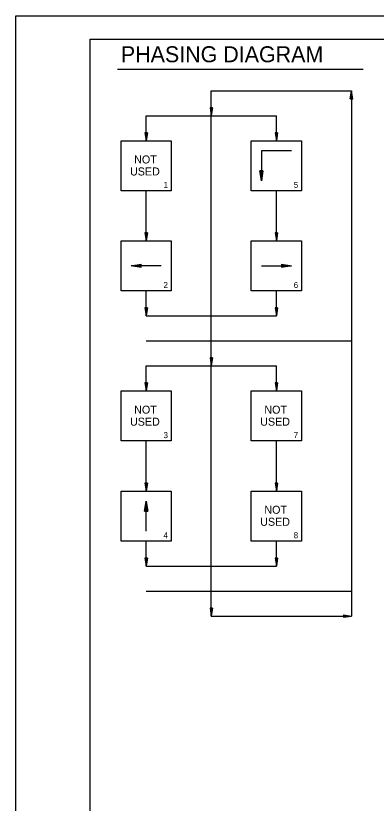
# Model space of a CAD drawing. Extents: x 1736833 to 1738623, y 544707 to 545544.
# Drawn here: x 1737623.4 to 1737803.3, y 544953.4 to 545346.8 of the extents above; entities that cross this region are included whole.
import ezdxf

# ---------------------------------------------------------------- set-up
doc = ezdxf.new("R2010")
doc.units = 0
for name, color, linetype in [('R_Border', 7, 'Continuous'), ('R_Draft', 7, 'Continuous'), ('R_No Plot', 7, 'Continuous'), ('T_Drafting', 7, 'Continuous'), ('T_Notes', 7, 'Continuous')]:
    doc.layers.add(name, color=color, linetype=linetype)

msp = doc.modelspace()

# ---------------------------------------------------------------- linework, layer by layer
at = {"layer": 'R_Border'}
for p, q in [((1737660.6, 545335.14), (1738609.14, 545335.14)), ((1737660.6, 544718.76), (1737660.6, 545335.14))]:
    msp.add_line(p, q, dxfattribs=at)
at = {"layer": 'R_Draft'}
msp.add_lwpolyline([(1737660.6, 545335.14), (1738362.36, 545335.14), (1738362.36, 545305.5), (1738475, 545295.74), (1738536.2, 545296.37), (1738536.2, 545224.37), (1738536.2, 545185.59), (1738536.2, 545175.9), (1738608.92, 545175.9), (1738609.14, 544767.79), (1738408.07, 544767.79), (1738257.64, 544767.79), (1738257.64, 544719.22), (1737660.6, 544718.76)], close=True, dxfattribs=at)
at = {"layer": 'R_No Plot'}
msp.add_line((1737623.4, 545346.82), (1738623.4, 545346.82), dxfattribs=at)
msp.add_lwpolyline([(1737623.38, 545346.82), (1738623.4, 545346.82), (1738623.4, 544706.81), (1737623.38, 544706.81)], close=True, dxfattribs=at)
at = {"layer": 'T_Drafting'}
for p, q in [((1737720.98, 545046.89), (1737720.98, 545309.39)), ((1737720.98, 545309.39), (1737790.98, 545309.39)), ((1737790.38, 545305.39), (1737790.98, 545309.39)), ((1737790.48, 545305.39), (1737790.98, 545308.73)), ((1737790.58, 545305.39), (1737790.98, 545308.04)), ((1737790.68, 545305.39), (1737790.98, 545307.37)), ((1737790.78, 545305.39), (1737790.98, 545306.69)), ((1737790.88, 545305.39), (1737790.98, 545306.03)), ((1737790.98, 545309.39), (1737790.98, 545046.89)), ((1737791.58, 545305.39), (1737790.98, 545309.39)), ((1737791.48, 545305.39), (1737790.98, 545308.73)), ((1737791.37, 545305.39), (1737790.98, 545308.04)), ((1737791.27, 545305.39), (1737790.98, 545307.37)), ((1737791.17, 545305.39), (1737790.98, 545306.69)), ((1737791.07, 545305.39), (1737790.98, 545306.03)), ((1737790.38, 545305.39), (1737791.58, 545305.39)), ((1737720.38, 545300.89), (1737720.98, 545296.89)), ((1737721.58, 545300.89), (1737720.38, 545300.89)), ((1737720.48, 545300.89), (1737720.98, 545297.56)), ((1737720.58, 545300.89), (1737720.98, 545298.25)), ((1737720.68, 545300.89), (1737720.98, 545298.92)), ((1737720.78, 545300.89), (1737720.98, 545299.59)), ((1737720.88, 545300.89), (1737720.98, 545300.26)), ((1737721.58, 545300.89), (1737720.98, 545296.89)), ((1737721.17, 545300.89), (1737720.98, 545299.59)), ((1737721.37, 545300.89), (1737720.98, 545298.25)), ((1737721.48, 545300.89), (1737720.98, 545297.56)), ((1737721.27, 545300.89), (1737720.98, 545298.92)), ((1737721.07, 545300.89), (1737720.98, 545300.26)), ((1737688.48, 545284.39), (1737688.48, 545296.89)), ((1737688.48, 545296.89), (1737753.48, 545296.89)), ((1737753.48, 545284.39), (1737753.48, 545296.89)), ((1737687.88, 545288.39), (1737688.48, 545284.39)), ((1737689.08, 545288.39), (1737687.88, 545288.39)), ((1737687.98, 545288.39), (1737688.48, 545285.06)), ((1737688.08, 545288.39), (1737688.48, 545285.75)), ((1737688.18, 545288.39), (1737688.48, 545286.42)), ((1737688.28, 545288.39), (1737688.48, 545287.09)), ((1737688.38, 545288.39), (1737688.48, 545287.76)), ((1737689.08, 545288.39), (1737688.48, 545284.39)), ((1737688.67, 545288.39), (1737688.48, 545287.09)), ((1737688.87, 545288.39), (1737688.48, 545285.75)), ((1737688.98, 545288.39), (1737688.48, 545285.06)), ((1737688.77, 545288.39), (1737688.48, 545286.42)), ((1737688.57, 545288.39), (1737688.48, 545287.76)), ((1737752.88, 545288.39), (1737753.48, 545284.39)), ((1737754.08, 545288.39), (1737752.88, 545288.39)), ((1737752.98, 545288.39), (1737753.48, 545285.06)), ((1737753.08, 545288.39), (1737753.48, 545285.75)), ((1737753.18, 545288.39), (1737753.48, 545286.42)), ((1737753.28, 545288.39), (1737753.48, 545287.09)), ((1737753.38, 545288.39), (1737753.48, 545287.76)), ((1737754.08, 545288.39), (1737753.48, 545284.39)), ((1737753.67, 545288.39), (1737753.48, 545287.09)), ((1737753.87, 545288.39), (1737753.48, 545285.75)), ((1737753.98, 545288.39), (1737753.48, 545285.06)), ((1737753.77, 545288.39), (1737753.48, 545286.42)), ((1737753.57, 545288.39), (1737753.48, 545287.76)), ((1737760.98, 545279.39), (1737745.98, 545279.39)), ((1737745.98, 545279.39), (1737745.98, 545264.39)), ((1737745.98, 545264.39), (1737745.23, 545269.39)), ((1737746.73, 545269.39), (1737745.23, 545269.39)), ((1737745.35, 545269.39), (1737745.98, 545265.23)), ((1737745.98, 545266.09), (1737745.48, 545269.39)), ((1737745.6, 545269.39), (1737745.98, 545266.92)), ((1737745.98, 545267.77), (1737745.73, 545269.39)), ((1737745.86, 545269.39), (1737745.98, 545268.6)), ((1737745.98, 545268.6), (1737746.09, 545269.39)), ((1737746.22, 545269.39), (1737745.98, 545267.77)), ((1737745.98, 545266.92), (1737746.35, 545269.39)), ((1737746.47, 545269.39), (1737745.98, 545266.09)), ((1737745.98, 545265.23), (1737746.6, 545269.39)), ((1737746.73, 545269.39), (1737745.98, 545264.39)), ((1737688.48, 545234.39), (1737688.48, 545259.39)), ((1737753.48, 545234.39), (1737753.48, 545259.39)), ((1737687.88, 545238.39), (1737688.48, 545234.39)), ((1737689.08, 545238.39), (1737687.88, 545238.39)), ((1737687.98, 545238.39), (1737688.48, 545235.06)), ((1737688.08, 545238.39), (1737688.48, 545235.75)), ((1737688.18, 545238.39), (1737688.48, 545236.42)), ((1737688.28, 545238.39), (1737688.48, 545237.09)), ((1737688.38, 545238.39), (1737688.48, 545237.76)), ((1737689.08, 545238.39), (1737688.48, 545234.39)), ((1737688.67, 545238.39), (1737688.48, 545237.09)), ((1737688.87, 545238.39), (1737688.48, 545235.75)), ((1737688.98, 545238.39), (1737688.48, 545235.06)), ((1737688.77, 545238.39), (1737688.48, 545236.42)), ((1737688.57, 545238.39), (1737688.48, 545237.76)), ((1737752.88, 545238.39), (1737753.48, 545234.39)), ((1737754.08, 545238.39), (1737752.88, 545238.39)), ((1737752.98, 545238.39), (1737753.48, 545235.06)), ((1737753.08, 545238.39), (1737753.48, 545235.75)), ((1737753.18, 545238.39), (1737753.48, 545236.42)), ((1737753.28, 545238.39), (1737753.48, 545237.09)), ((1737753.38, 545238.39), (1737753.48, 545237.76)), ((1737754.08, 545238.39), (1737753.48, 545234.39)), ((1737753.67, 545238.39), (1737753.48, 545237.09)), ((1737753.87, 545238.39), (1737753.48, 545235.75)), ((1737753.98, 545238.39), (1737753.48, 545235.06)), ((1737753.77, 545238.39), (1737753.48, 545236.42)), ((1737753.57, 545238.39), (1737753.48, 545237.76)), ((1737680.98, 545221.89), (1737685.98, 545222.64)), ((1737695.98, 545221.89), (1737680.98, 545221.89)), ((1737685.98, 545221.14), (1737680.98, 545221.89)), ((1737685.98, 545222.52), (1737681.81, 545221.89)), ((1737681.81, 545221.89), (1737685.98, 545221.27)), ((1737682.67, 545221.89), (1737685.98, 545222.39)), ((1737685.98, 545221.4), (1737682.67, 545221.89)), ((1737685.98, 545222.27), (1737683.5, 545221.89)), ((1737683.5, 545221.89), (1737685.98, 545221.52)), ((1737684.35, 545221.89), (1737685.98, 545222.14)), ((1737685.98, 545221.65), (1737684.35, 545221.89)), ((1737685.98, 545222.01), (1737685.19, 545221.89)), ((1737685.19, 545221.89), (1737685.98, 545221.78)), ((1737685.98, 545221.14), (1737685.98, 545222.64)), ((1737745.98, 545221.89), (1737760.98, 545221.89)), ((1737755.98, 545222.64), (1737760.98, 545221.89)), ((1737755.98, 545222.64), (1737755.98, 545221.14)), ((1737760.14, 545221.89), (1737755.98, 545222.52)), ((1737755.98, 545222.39), (1737759.28, 545221.89)), ((1737758.45, 545221.89), (1737755.98, 545222.27)), ((1737755.98, 545222.14), (1737757.6, 545221.89)), ((1737756.77, 545221.89), (1737755.98, 545222.01)), ((1737760.98, 545221.89), (1737755.98, 545221.14)), ((1737755.98, 545221.27), (1737760.14, 545221.89)), ((1737759.28, 545221.89), (1737755.98, 545221.4)), ((1737755.98, 545221.52), (1737758.45, 545221.89)), ((1737757.6, 545221.89), (1737755.98, 545221.65)), ((1737755.98, 545221.78), (1737756.77, 545221.89)), ((1737688.48, 545196.89), (1737688.48, 545209.39)), ((1737753.48, 545196.89), (1737753.48, 545209.39)), ((1737687.88, 545200.89), (1737688.48, 545196.89)), ((1737689.08, 545200.89), (1737687.88, 545200.89)), ((1737687.98, 545200.89), (1737688.48, 545197.56)), ((1737688.08, 545200.89), (1737688.48, 545198.25)), ((1737688.18, 545200.89), (1737688.48, 545198.92)), ((1737688.28, 545200.89), (1737688.48, 545199.59)), ((1737688.38, 545200.89), (1737688.48, 545200.26)), ((1737689.08, 545200.89), (1737688.48, 545196.89)), ((1737688.67, 545200.89), (1737688.48, 545199.59)), ((1737688.87, 545200.89), (1737688.48, 545198.25)), ((1737688.98, 545200.89), (1737688.48, 545197.56)), ((1737688.77, 545200.89), (1737688.48, 545198.92)), ((1737688.57, 545200.89), (1737688.48, 545200.26)), ((1737752.88, 545200.89), (1737753.48, 545196.89)), ((1737754.08, 545200.89), (1737752.88, 545200.89)), ((1737752.98, 545200.89), (1737753.48, 545197.56)), ((1737753.08, 545200.89), (1737753.48, 545198.25)), ((1737753.18, 545200.89), (1737753.48, 545198.92)), ((1737753.28, 545200.89), (1737753.48, 545199.59)), ((1737753.38, 545200.89), (1737753.48, 545200.26)), ((1737754.08, 545200.89), (1737753.48, 545196.89)), ((1737753.67, 545200.89), (1737753.48, 545199.59)), ((1737753.87, 545200.89), (1737753.48, 545198.25)), ((1737753.98, 545200.89), (1737753.48, 545197.56)), ((1737753.77, 545200.89), (1737753.48, 545198.92)), ((1737753.57, 545200.89), (1737753.48, 545200.26)), ((1737688.48, 545196.89), (1737753.48, 545196.89)), ((1737688.48, 545184.39), (1737790.98, 545184.39)), ((1737720.38, 545175.89), (1737720.98, 545171.89)), ((1737721.58, 545175.89), (1737720.38, 545175.89)), ((1737720.48, 545175.89), (1737720.98, 545172.56)), ((1737720.58, 545175.89), (1737720.98, 545173.25)), ((1737720.68, 545175.89), (1737720.98, 545173.92)), ((1737720.78, 545175.89), (1737720.98, 545174.59)), ((1737720.88, 545175.89), (1737720.98, 545175.26)), ((1737721.58, 545175.89), (1737720.98, 545171.89)), ((1737721.17, 545175.89), (1737720.98, 545174.59)), ((1737721.37, 545175.89), (1737720.98, 545173.25)), ((1737721.48, 545175.89), (1737720.98, 545172.56)), ((1737721.27, 545175.89), (1737720.98, 545173.92)), ((1737721.07, 545175.89), (1737720.98, 545175.26)), ((1737688.48, 545171.89), (1737753.48, 545171.89)), ((1737688.48, 545159.39), (1737688.48, 545171.89)), ((1737753.48, 545159.39), (1737753.48, 545171.89)), ((1737687.88, 545163.39), (1737688.48, 545159.39)), ((1737689.08, 545163.39), (1737687.88, 545163.39)), ((1737687.98, 545163.39), (1737688.48, 545160.06)), ((1737688.08, 545163.39), (1737688.48, 545160.75)), ((1737688.18, 545163.39), (1737688.48, 545161.42)), ((1737688.28, 545163.39), (1737688.48, 545162.09)), ((1737688.38, 545163.39), (1737688.48, 545162.76)), ((1737689.08, 545163.39), (1737688.48, 545159.39)), ((1737688.67, 545163.39), (1737688.48, 545162.09)), ((1737688.87, 545163.39), (1737688.48, 545160.75)), ((1737688.98, 545163.39), (1737688.48, 545160.06)), ((1737688.77, 545163.39), (1737688.48, 545161.42)), ((1737688.57, 545163.39), (1737688.48, 545162.76)), ((1737752.88, 545163.39), (1737753.48, 545159.39)), ((1737754.08, 545163.39), (1737752.88, 545163.39)), ((1737752.98, 545163.39), (1737753.48, 545160.06)), ((1737753.08, 545163.39), (1737753.48, 545160.75)), ((1737753.18, 545163.39), (1737753.48, 545161.42)), ((1737753.28, 545163.39), (1737753.48, 545162.09)), ((1737753.38, 545163.39), (1737753.48, 545162.76)), ((1737754.08, 545163.39), (1737753.48, 545159.39)), ((1737753.67, 545163.39), (1737753.48, 545162.09)), ((1737753.87, 545163.39), (1737753.48, 545160.75)), ((1737753.98, 545163.39), (1737753.48, 545160.06)), ((1737753.77, 545163.39), (1737753.48, 545161.42)), ((1737753.57, 545163.39), (1737753.48, 545162.76)), ((1737688.48, 545109.39), (1737688.48, 545134.39)), ((1737753.48, 545109.39), (1737753.48, 545134.39)), ((1737687.88, 545113.39), (1737688.48, 545109.39)), ((1737689.08, 545113.39), (1737687.88, 545113.39)), ((1737687.98, 545113.39), (1737688.48, 545110.06)), ((1737688.08, 545113.39), (1737688.48, 545110.75)), ((1737688.18, 545113.39), (1737688.48, 545111.42)), ((1737688.28, 545113.39), (1737688.48, 545112.09)), ((1737688.38, 545113.39), (1737688.48, 545112.76)), ((1737689.08, 545113.39), (1737688.48, 545109.39)), ((1737688.67, 545113.39), (1737688.48, 545112.09)), ((1737688.87, 545113.39), (1737688.48, 545110.75)), ((1737688.98, 545113.39), (1737688.48, 545110.06)), ((1737688.77, 545113.39), (1737688.48, 545111.42)), ((1737688.57, 545113.39), (1737688.48, 545112.76)), ((1737752.88, 545113.39), (1737753.48, 545109.39)), ((1737754.08, 545113.39), (1737752.88, 545113.39)), ((1737752.98, 545113.39), (1737753.48, 545110.06)), ((1737753.08, 545113.39), (1737753.48, 545110.75)), ((1737753.18, 545113.39), (1737753.48, 545111.42)), ((1737753.28, 545113.39), (1737753.48, 545112.09)), ((1737753.38, 545113.39), (1737753.48, 545112.76)), ((1737754.08, 545113.39), (1737753.48, 545109.39)), ((1737753.67, 545113.39), (1737753.48, 545112.09)), ((1737753.87, 545113.39), (1737753.48, 545110.75)), ((1737753.98, 545113.39), (1737753.48, 545110.06)), ((1737753.77, 545113.39), (1737753.48, 545111.42)), ((1737753.57, 545113.39), (1737753.48, 545112.76)), ((1737687.73, 545099.39), (1737688.48, 545104.39)), ((1737688.48, 545103.56), (1737687.85, 545099.39)), ((1737687.98, 545099.39), (1737688.48, 545102.7)), ((1737688.48, 545101.87), (1737688.1, 545099.39)), ((1737688.48, 545089.39), (1737688.48, 545104.39)), ((1737688.48, 545104.39), (1737689.23, 545099.39)), ((1737689.1, 545099.39), (1737688.48, 545103.56)), ((1737688.48, 545102.7), (1737688.97, 545099.39)), ((1737688.85, 545099.39), (1737688.48, 545101.87)), ((1737687.73, 545099.39), (1737689.23, 545099.39)), ((1737688.23, 545099.39), (1737688.48, 545101.02)), ((1737688.48, 545100.18), (1737688.36, 545099.39)), ((1737688.48, 545101.02), (1737688.72, 545099.39)), ((1737688.59, 545099.39), (1737688.48, 545100.18)), ((1737688.48, 545071.89), (1737688.48, 545084.39)), ((1737753.48, 545071.89), (1737753.48, 545084.39)), ((1737687.88, 545075.89), (1737688.48, 545071.89)), ((1737689.08, 545075.89), (1737687.88, 545075.89)), ((1737687.98, 545075.89), (1737688.48, 545072.56)), ((1737688.08, 545075.89), (1737688.48, 545073.25)), ((1737688.18, 545075.89), (1737688.48, 545073.92)), ((1737688.28, 545075.89), (1737688.48, 545074.59)), ((1737688.38, 545075.89), (1737688.48, 545075.26)), ((1737689.08, 545075.89), (1737688.48, 545071.89)), ((1737688.67, 545075.89), (1737688.48, 545074.59)), ((1737688.87, 545075.89), (1737688.48, 545073.25)), ((1737688.98, 545075.89), (1737688.48, 545072.56)), ((1737688.77, 545075.89), (1737688.48, 545073.92)), ((1737688.57, 545075.89), (1737688.48, 545075.26)), ((1737752.88, 545075.89), (1737753.48, 545071.89)), ((1737754.08, 545075.89), (1737752.88, 545075.89)), ((1737752.98, 545075.89), (1737753.48, 545072.56)), ((1737753.08, 545075.89), (1737753.48, 545073.25)), ((1737753.18, 545075.89), (1737753.48, 545073.92)), ((1737753.28, 545075.89), (1737753.48, 545074.59)), ((1737753.38, 545075.89), (1737753.48, 545075.26)), ((1737754.08, 545075.89), (1737753.48, 545071.89)), ((1737753.67, 545075.89), (1737753.48, 545074.59)), ((1737753.87, 545075.89), (1737753.48, 545073.25)), ((1737753.98, 545075.89), (1737753.48, 545072.56)), ((1737753.77, 545075.89), (1737753.48, 545073.92)), ((1737753.57, 545075.89), (1737753.48, 545075.26)), ((1737688.48, 545071.89), (1737753.48, 545071.89)), ((1737688.48, 545059.39), (1737790.98, 545059.39)), ((1737720.38, 545050.89), (1737720.98, 545046.89)), ((1737721.58, 545050.89), (1737720.38, 545050.89)), ((1737720.48, 545050.89), (1737720.98, 545047.56)), ((1737720.58, 545050.89), (1737720.98, 545048.25)), ((1737720.68, 545050.89), (1737720.98, 545048.92)), ((1737720.78, 545050.89), (1737720.98, 545049.59)), ((1737720.88, 545050.89), (1737720.98, 545050.26)), ((1737721.58, 545050.89), (1737720.98, 545046.89)), ((1737721.17, 545050.89), (1737720.98, 545049.59)), ((1737721.37, 545050.89), (1737720.98, 545048.25)), ((1737721.48, 545050.89), (1737720.98, 545047.56)), ((1737721.27, 545050.89), (1737720.98, 545048.92)), ((1737721.07, 545050.89), (1737720.98, 545050.26)), ((1737720.98, 545046.89), (1737790.98, 545046.89)), ((1737786.98, 545047.49), (1737790.98, 545046.89)), ((1737786.98, 545047.49), (1737786.98, 545046.29)), ((1737786.98, 545047.39), (1737790.31, 545046.89)), ((1737786.98, 545047.29), (1737789.62, 545046.89)), ((1737786.98, 545047.19), (1737788.95, 545046.89)), ((1737786.98, 545047.09), (1737788.28, 545046.89)), ((1737786.98, 545046.99), (1737787.61, 545046.89)), ((1737786.98, 545046.29), (1737790.98, 545046.89)), ((1737786.98, 545046.7), (1737788.28, 545046.89)), ((1737786.98, 545046.5), (1737789.62, 545046.89)), ((1737786.98, 545046.39), (1737790.31, 545046.89)), ((1737786.98, 545046.6), (1737788.95, 545046.89)), ((1737786.98, 545046.8), (1737787.61, 545046.89))]:
    msp.add_line(p, q, dxfattribs=at)
for points in [[(1737675.98, 545284.39), (1737700.98, 545284.39), (1737700.98, 545259.39), (1737675.98, 545259.39)], [(1737740.98, 545284.39), (1737765.98, 545284.39), (1737765.98, 545259.39), (1737740.98, 545259.39)], [(1737675.98, 545234.39), (1737700.98, 545234.39), (1737700.98, 545209.39), (1737675.98, 545209.39)], [(1737740.98, 545234.39), (1737765.98, 545234.39), (1737765.98, 545209.39), (1737740.98, 545209.39)], [(1737675.98, 545159.39), (1737700.98, 545159.39), (1737700.98, 545134.39), (1737675.98, 545134.39)], [(1737740.98, 545159.39), (1737765.98, 545159.39), (1737765.98, 545134.39), (1737740.98, 545134.39)], [(1737675.98, 545109.39), (1737700.98, 545109.39), (1737700.98, 545084.39), (1737675.98, 545084.39)], [(1737740.98, 545109.39), (1737765.98, 545109.39), (1737765.98, 545084.39), (1737740.98, 545084.39)]]:
    msp.add_lwpolyline(points, close=True, dxfattribs=at)
at = {"layer": 'T_Notes'}
msp.add_line((1737674.25, 545320.11), (1737796.89, 545320.11), dxfattribs=at)

# ---------------------------------------------------------------- texts
at = {"layer": 'T_Drafting'}
for s, height, p in [('NOT', 4, (1737682.49, 545273.03)), ('USED', 4, (1737680.42, 545267.03)), ('1', 3, (1737697.13, 545260.82)), ('5', 3, (1737762.13, 545260.82)), ('2', 3, (1737697.13, 545210.82)), ('6', 3, (1737762.13, 545210.82)), ('NOT', 4, (1737682.49, 545148.03)), ('NOT', 4, (1737747.49, 545148.03)), ('USED', 4, (1737680.42, 545142.03)), ('USED', 4, (1737745.42, 545142.03)), ('3', 3, (1737697.13, 545135.82)), ('7', 3, (1737762.13, 545135.82)), ('NOT', 4, (1737747.49, 545098.03)), ('USED', 4, (1737745.42, 545092.03)), ('4', 3, (1737697.13, 545085.82)), ('8', 3, (1737762.13, 545085.82))]:
    msp.add_text(s, height=height, dxfattribs=at).set_placement(p)
at = {"layer": 'T_Notes'}
msp.add_text('PHASING DIAGRAM', height=8, dxfattribs=at).set_placement((1737675.85, 545323.58))

doc.saveas('drawing.dxf')
